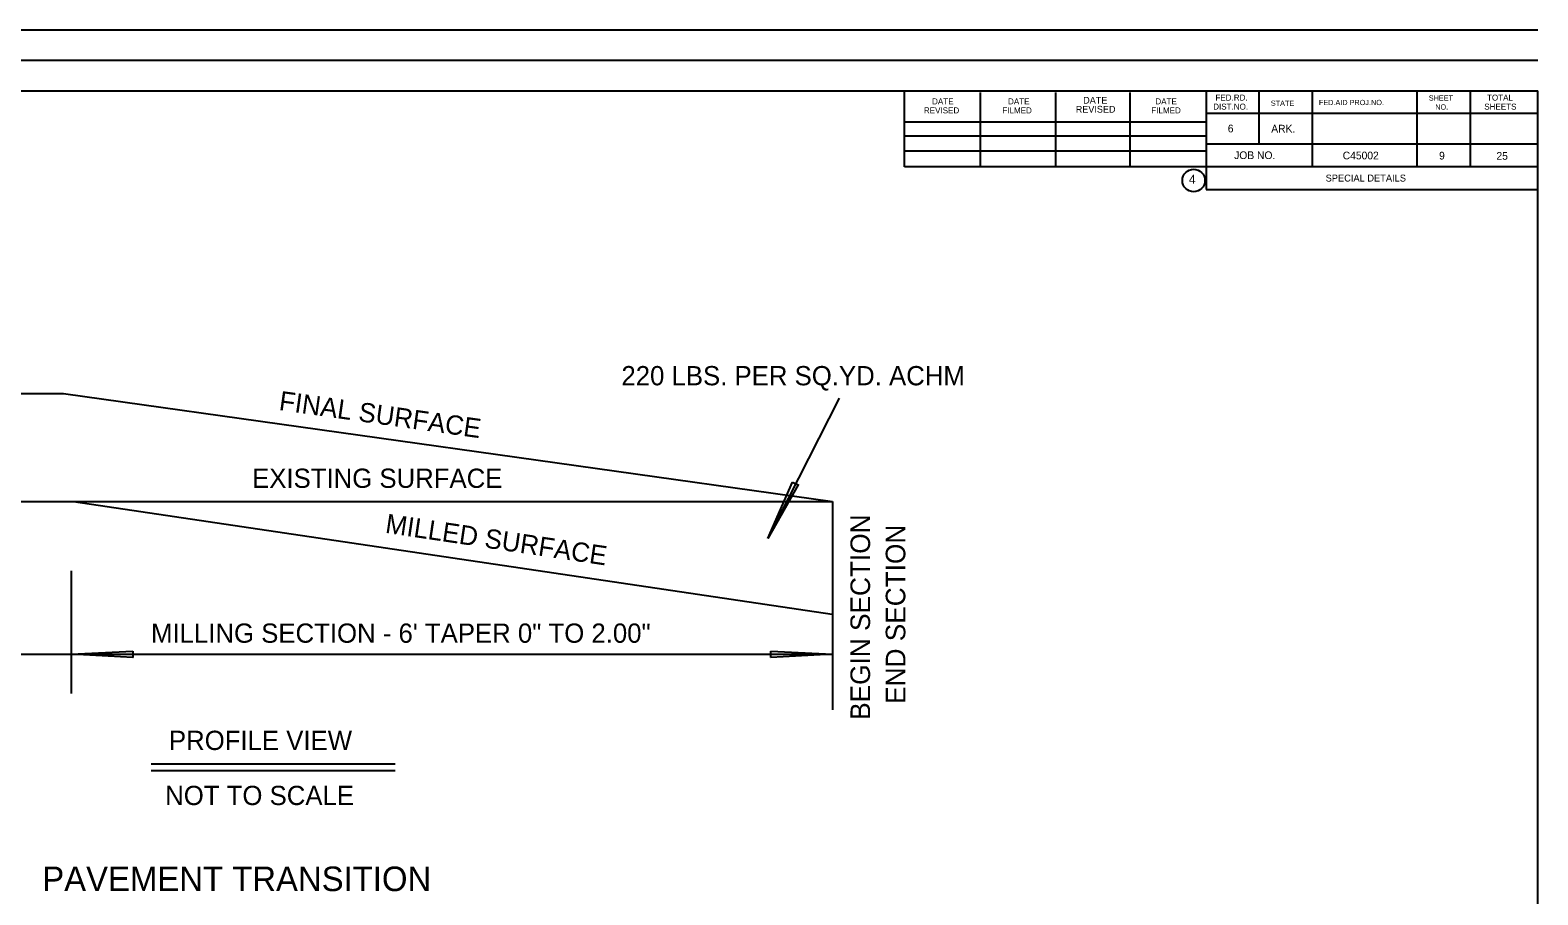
# Model space of a CAD drawing. Extents: x 1944905 to 1956777, y 763871 to 764977.
# Drawn here: x 1954088 to 1955068, y 764415 to 764977 of the extents above; entities that cross this region are included whole.
import ezdxf

# ---------------------------------------------------------------- set-up
doc = ezdxf.new("R2010")
doc.units = 0
for name, color, linetype in [('Default', 7, 'Continuous'), ('R_Border', 7, 'Continuous'), ('R_Dimension', 7, 'Continuous')]:
    doc.layers.add(name, color=color, linetype=linetype)

# ---------------------------------------------------------------- blocks, each defined once
blk = doc.blocks.new('AHD')
at = {"layer": 'R_Dimension'}
for p, q in [((0, 0), (0.796, 1.837)), ((0.975, 1.749), (0, 0)), ((0.796, 1.837), (0.975, 1.749)), ((0.978, 1.754), (0.975, 1.749))]:
    blk.add_line(p, q, dxfattribs=at)

msp = doc.modelspace()

# ---------------------------------------------------------------- linework, layer by layer
at = {"layer": 'Default'}
for p, q in [((1955067.69, 764976.71), (1953449.02, 764976.71)), ((1955067.69, 764957.02), (1953449.02, 764957.02)), ((1953486.78, 764937.29), (1955067.69, 764937.29)), ((1954656.37, 764887.95), (1954656.37, 764937.29)), ((1954852.26, 764937.29), (1954852.26, 764873.29)), ((1954886.46, 764937.29), (1954886.46, 764902.6)), ((1954921.14, 764937.29), (1954921.14, 764887.95)), ((1954989.04, 764937.29), (1954989.04, 764887.95)), ((1955023.72, 764937.29), (1955023.72, 764887.95)), ((1955067.69, 763910.07), (1955067.69, 764937.29)), ((1954705.71, 764887.95), (1954705.71, 764936.31)), ((1954754.56, 764887.95), (1954754.56, 764936.31)), ((1954802.92, 764887.95), (1954802.92, 764936.31)), ((1954656.37, 764917.26), (1954852.26, 764917.26)), ((1955067.69, 764922.63), (1954852.26, 764922.63)), ((1954656.37, 764907.98), (1954852.26, 764907.98)), ((1954656.37, 764898.21), (1954852.26, 764898.21)), ((1955067.69, 764902.6), (1954852.26, 764902.6)), ((1955067.69, 764887.95), (1954656.37, 764887.95)), ((1954852.26, 764873.29), (1955067.69, 764873.29))]:
    msp.add_line(p, q, dxfattribs=at)
msp.add_circle((1954844.15, 764879.01), 7.33, dxfattribs=at)
at = {"layer": 'R_Dimension'}
for p, q in [((1953915.95, 764740.97), (1954110.06, 764740.68)), ((1954110.06, 764740.68), (1954609.62, 764670.5)), ((1954613.91, 764737.63), (1954567.51, 764646.46)), ((1953913.23, 764670.5), (1954116.62, 764670.5)), ((1954116.62, 764670.5), (1954609.47, 764597.41)), ((1954116.62, 764670.5), (1954609.62, 764670.5)), ((1954609.62, 764670.5), (1954609.62, 764535.1)), ((1954115.16, 764625.55), (1954115.16, 764545.87)), ((1953868.93, 764571.28), (1954609.62, 764571.28)), ((1954167.09, 764500.01), (1954325.61, 764500.01)), ((1954167.07, 764495.7), (1954325.64, 764495.7))]:
    msp.add_line(p, q, dxfattribs=at)

# ---------------------------------------------------------------- block references
at = {"layer": 'R_Border', "xscale": 20.32394048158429, "yscale": 19.95381106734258}
msp.add_blockref('AHD', (1954567.5, 764646.46), dxfattribs=at)
at = {"layer": 'R_Border'}
for p, xscale, yscale, rotation in [((1954115.16, 764571.28), 20.323922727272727, 19.953793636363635, -63.29422944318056), ((1954609.66, 764571.34), 20.323922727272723, 19.95379363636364, 116.78651893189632)]:
    msp.add_blockref('AHD', p, dxfattribs=dict(at, xscale=xscale, yscale=yscale, rotation=rotation))

# ---------------------------------------------------------------- texts
at = {"layer": 'Default'}
for s, height, p in [('DATE', 3.91, (1954674.27, 764928.49)), ('DATE', 3.91, (1954723.61, 764928.49)), ('REVISED', 4.396, (1954767.58, 764923.12)), ('DATE', 4.396, (1954772.41, 764928.98)), ('DATE', 3.91, (1954819.3, 764928.49)), ('DIST.NO.', 3.91, (1954856.85, 764925.08)), ('FED.RD.', 3.91, (1954858.3, 764930.94)), ('STATE', 3.42, (1954894.26, 764927.52)), ('FED.AID PROJ.NO.', 3.4203, (1954925.49, 764928.01)), ('SHEET', 3.42, (1954996.86, 764930.94)), ('NO.', 3.42, (1955001.05, 764925.08)), ('SHEETS', 3.91, (1955032.9, 764925.08)), ('TOTAL', 3.91, (1955034.69, 764930.94)), ('REVISED', 3.91, (1954668.96, 764922.63)), ('FILMED', 3.91, (1954719.91, 764922.63)), ('FILMED', 3.91, (1954816.63, 764922.63)), ('6', 5, (1954866.33, 764910.32)), ('ARK.', 5, (1954894.54, 764910.21)), ('JOB NO.', 5, (1954870.45, 764892.97)), ('C45002', 5, (1954940.96, 764892.78)), ('9', 5, (1955003.54, 764892.68)), ('25', 5, (1955040.8, 764892.51)), ('4', 5.86, (1954841.06, 764876.89)), ('SPECIAL DETAILS', 4.5, (1954929.87, 764878.37))]:
    msp.add_text(s, height=height, dxfattribs=at).set_placement(p)
at = {"layer": 'R_Dimension'}
for s, height, p in [('220 LBS. PER SQ.YD. ACHM', 12.5044, (1954472.51, 764746)), ('EXISTING SURFACE', 12.5044, (1954232.63, 764679.38)), ('MILLING SECTION - 6\' TAPER 0" TO 2.00"', 12.5044, (1954167.01, 764578.76)), ('PROFILE VIEW', 12.5044, (1954178.63, 764509.11)), ('NOT TO SCALE', 12.5044, (1954176.19, 764473.33)), ('PAVEMENT TRANSITION', 15.963, (1954096.36, 764417.43))]:
    msp.add_text(s, height=height, dxfattribs=at).set_placement(p)
for s, height, rotation, p in [('FINAL SURFACE', 12.5091, 352.00338, (1954249.64, 764730)), ('MILLED SURFACE', 12.5096, 351.56391, (1954318.66, 764650.24)), ('BEGIN SECTION', 12.7363, 90, (1954634, 764528.68)), ('END SECTION', 12.7363, 90, (1954656.9, 764539.06))]:
    msp.add_text(s, height=height, rotation=rotation, dxfattribs=at).set_placement(p)

doc.saveas('drawing.dxf')
